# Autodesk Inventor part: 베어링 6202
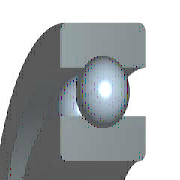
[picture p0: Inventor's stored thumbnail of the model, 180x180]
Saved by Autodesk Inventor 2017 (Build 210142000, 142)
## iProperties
IsCustomPart: 1
Created: 2015-09
Part Number: 베어링 6202
Material: 강, 연강
Description: 깊은 그루브 볼 베어링
Document SubType Name: Modeling
Standard: KS B 2023
Designer: mduedu
Standards Organization: KS
Language: ko-KR
Size Designation: 6202 - 15 x 35 x 11
Categories: <MemberInstance><Categories><Category DisplayName="샤프트 부품" InternalName="7f7aeb1f-a693-4053-b835-cee3144e0d98" Mnemonic="SHFT"><Category DisplayName="베어링" Inter
Density: 7.86 g/cm^3
Mass: 45.8725 g
Surface Area: 51.5584 cm^2
Volume: 5.83619 cm^3
Appearance: 노란색
Author: mduedu
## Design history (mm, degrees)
sketch "스케치" dims "d0" = 5.2 (= -0.26 x WD + 0.26 x BD)
  geometry: L1 (2.9, 12.5)-(8.1, 12.5); L2 (5.5, 12.5)-(5.5, 9.9); L3 (5.5, 12.5)-(5.5, 15.1); L4 (3.568, 10.76)-(0, 10.76); L5 (0, 7.5)-(11, 7.5); L6 (3.568, 14.24)-(0, 14.24); L7 (0, 17.5)-(11, 17.5); L8 (11, 7.5)-(11, 10.76); L9 (7.432, 10.76)-(11, 10.76); L10 (7.432, 14.24)-(11, 14.24); L11 (11, 17.5)-(11, 14.24); L12 (-1.4, 0)-(8.4, 0) reference; L13 (0, -0.3)-(0, 5.3) reference
  constraints: 22 end point, 4 point on line, 2 collinear, 2 perpendicular, 2 symmetric about line, 1 midpoint, 1 parallel, 14 other
  dimensions: "d9" = 15 diameter of L5 L12 (= WD); "d11" = 35 diameter of L7 L12 (= BD); "d12" = 11 distance between parallel lines of L8 L13 (= KB); "d13" = 21.52 diameter of L9 L12 (= 0.326 x BD + 0.674 x WD)
revolve "본체" stored, may be unused: angle "d6" = 90 deg
revolve "볼" stored, may be unused: angle "d7" = 90 deg
pattern_circular "IDS_ARRAYBALL[SIMPL:T]" dims angle "d3" = 360 deg
body "Solid1"
fillet "모깎기1" dims "d1" = 0.6 (= KRS)
other parameters: "WD" = 15 [user parameter; used in 5 equation terms], "BD" = 35 [user parameter; used in 5 equation terms], "KB" = 11 [user parameter; used in 1 equation term], "KRS" = 0.6 [user parameter; used in 1 equation term], "d4" = 0, "d5" = 0, "d8" = 0, "d14" = 0, "d15" = 0, "BBA" = 0 [user parameter], "BC0" = 3750000 [user parameter], "BC" = 7800000 [user parameter], "BR" = 17.5 (= 0.5 x BD) [user parameter], "WR" = 7.5 (= 0.5 x WD) [user parameter]
